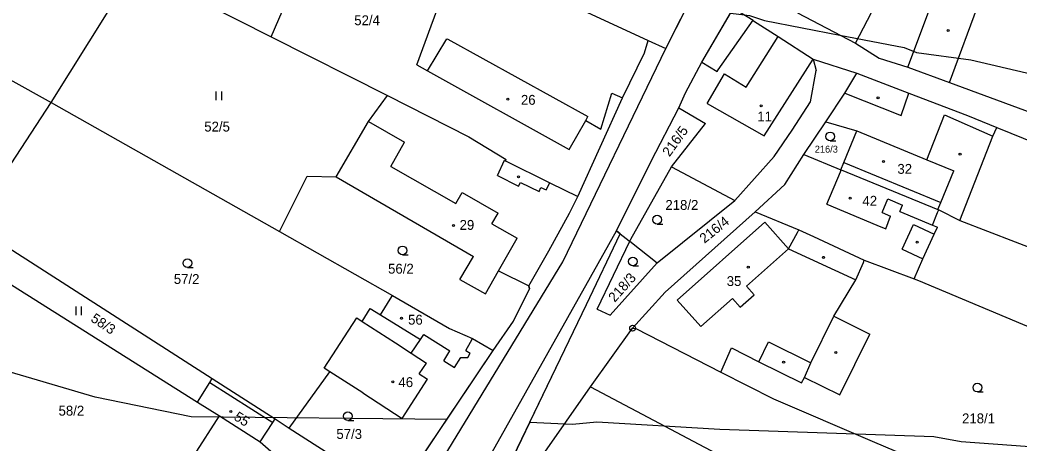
# Model space of a CAD drawing. Extents: x -743888 to -742027, y -1128394 to -1126768.
# Drawn here: x -743087.8 to -742915.5, y -1127647.7 to -1127574.7 of the extents above; entities that cross this region are included whole.
import ezdxf

# ---------------------------------------------------------------- set-up
doc = ezdxf.new("R2010")
doc.units = 0
for name, color, linetype in [('Vrstva 1', 7, 'Continuous'), ('Vrstva 18', 7, 'Continuous'), ('Vrstva 19', 7, 'Continuous'), ('Vrstva 24', 7, 'Continuous'), ('Vrstva 25', 7, 'Continuous'), ('Vrstva 3', 7, 'Continuous'), ('Vrstva 37', 7, 'Continuous'), ('Vrstva 4', 7, 'Continuous'), ('Vrstva 52', 7, 'Continuous'), ('Vrstva 6', 7, 'Continuous')]:
    doc.layers.add(name, color=color, linetype=linetype)

msp = doc.modelspace()

# ---------------------------------------------------------------- linework, layer by layer
at = {"layer": 'Vrstva 1'}
for p, q in [((-743035.35, -1127634.62), (-743029.73, -1127625.98)), ((-743029.73, -1127625.98), (-743028.79, -1127626.59)), ((-743034.37, -1127635.25), (-743035.35, -1127634.62)), ((-743028.68, -1127638.9), (-743034.37, -1127635.25))]:
    msp.add_line(p, q, dxfattribs=at)
for points in [[(-743016.9, -1127575.68), (-743012.24, -1127563.05)], [(-743067.95, -1127565.66), (-743044.5, -1127577.53)], [(-743044.5, -1127577.53), (-743039.4, -1127565.75)], [(-743001.38, -1127568.05), (-742979.47, -1127578.16)], [(-742976.43, -1127579.56), (-742971.19, -1127569.17)], [(-742927.53, -1127585.44), (-742922.25, -1127571.32)], [(-743082.43, -1127588.87), (-743072.64, -1127573.17)], [(-742970.21, -1127581.92), (-742964.75, -1127572.6)], [(-742964.75, -1127572.6), (-742961.39, -1127574.71)], [(-742953.72, -1127573.43), (-742943.72, -1127578.66)], [(-743019.38, -1127582.4), (-743016.9, -1127575.68)], [(-742961.39, -1127574.71), (-742961.32, -1127574.78)], [(-742961.32, -1127574.78), (-742957.06, -1127577.5)], [(-743044.5, -1127577.53), (-743024.44, -1127587.67)], [(-742957.06, -1127577.5), (-742951.01, -1127581.4)], [(-742980.12, -1127580.33), (-742979.47, -1127578.16)], [(-742979.47, -1127578.16), (-742976.43, -1127579.56)], [(-742943.72, -1127578.66), (-742939.64, -1127581.23)], [(-742983.9, -1127588.07), (-742980.12, -1127580.33)], [(-743019.38, -1127582.4), (-743017.56, -1127583.41)], [(-742973.05, -1127587.2), (-742970.21, -1127581.92)], [(-742951.01, -1127581.4), (-742943.48, -1127583.82)], [(-742951.01, -1127581.4), (-742950.51, -1127583.33)], [(-742939.64, -1127581.23), (-742934.7, -1127582.76)], [(-742934.7, -1127582.76), (-742927.53, -1127585.44)], [(-743017.56, -1127583.41), (-742993.08, -1127596.96)], [(-742951.47, -1127588.73), (-742950.51, -1127583.33)], [(-742945.53, -1127587.26), (-742943.48, -1127583.82)], [(-742943.48, -1127583.82), (-742934.51, -1127587.27)], [(-742927.53, -1127585.44), (-742896.8, -1127596.74)], [(-743027.7, -1127592.11), (-743024.44, -1127587.67)], [(-743024.44, -1127587.67), (-743010.42, -1127594.79)], [(-742985.72, -1127587.27), (-742983.9, -1127588.07)], [(-742974.2, -1127589.77), (-742973.05, -1127587.2)], [(-742948.85, -1127592.21), (-742945.53, -1127587.26)], [(-742934.51, -1127587.27), (-742924.42, -1127591.13)], [(-743096.19, -1127609.82), (-743082.43, -1127588.87)], [(-743082.43, -1127588.87), (-743043.08, -1127611.1)], [(-742991.6, -1127605.04), (-742983.9, -1127588.07)], [(-742954.62, -1127593.61), (-742951.47, -1127588.73)], [(-742978.95, -1127598.97), (-742974.2, -1127589.77)], [(-742924.42, -1127591.13), (-742919.33, -1127593.19)], [(-743033.28, -1127601.65), (-743027.7, -1127592.11)], [(-742993.08, -1127596.96), (-742990.26, -1127591.96)], [(-742952.62, -1127597.82), (-742948.85, -1127592.21)], [(-742948.85, -1127592.21), (-742943.5, -1127593.76)], [(-742920.01, -1127594.66), (-742919.33, -1127593.19)], [(-742919.33, -1127593.19), (-742898.48, -1127601.61)], [(-743010.42, -1127594.79), (-743003.98, -1127598.66)], [(-742957.73, -1127598.16), (-742954.62, -1127593.61)], [(-742945.74, -1127599.22), (-742943.5, -1127593.76)], [(-742925.74, -1127609.17), (-742920.01, -1127594.66)], [(-742964.56, -1127605.74), (-742957.73, -1127598.16)], [(-742955.92, -1127602.99), (-742952.62, -1127597.82)], [(-742952.62, -1127597.82), (-742946.24, -1127600.44)], [(-743004.09, -1127598.89), (-743003.98, -1127598.66)], [(-743004.09, -1127598.89), (-742996.47, -1127602.7)], [(-742984.97, -1127610.98), (-742978.95, -1127598.97)], [(-742982.46, -1127612.4), (-742975.48, -1127599.94)], [(-742975.48, -1127599.94), (-742964.56, -1127605.74)], [(-742946.24, -1127600.44), (-742945.74, -1127599.22)], [(-743043.08, -1127611.1), (-743038.28, -1127601.54)], [(-743038.28, -1127601.54), (-743033.28, -1127601.65)], [(-743033.28, -1127601.65), (-743009.6, -1127615.39)], [(-742946.24, -1127600.44), (-742946.19, -1127600.46)], [(-742946.19, -1127600.46), (-742929.52, -1127607.31)], [(-742996.47, -1127602.7), (-742991.6, -1127605.04)], [(-742961.05, -1127607.72), (-742955.92, -1127602.99)], [(-742993.07, -1127607.9), (-742991.6, -1127605.04)], [(-742977.94, -1127616.47), (-742964.56, -1127605.74)], [(-742996.62, -1127614.4), (-742993.07, -1127607.9)], [(-742976.55, -1127621.53), (-742961.05, -1127607.72)], [(-742961.05, -1127607.72), (-742953.51, -1127610.79)], [(-742930.45, -1127609.97), (-742929.56, -1127607.84)], [(-742929.56, -1127607.84), (-742929.36, -1127607.37)], [(-742929.52, -1127607.31), (-742929.36, -1127607.37)], [(-742929.36, -1127607.37), (-742925.74, -1127609.17)], [(-743096.19, -1127609.82), (-743054.68, -1127636.42)], [(-742930.45, -1127609.97), (-742929.58, -1127610.33)], [(-742930.16, -1127611.56), (-742929.58, -1127610.33)], [(-742925.74, -1127609.17), (-742892.31, -1127622.04)], [(-743043.08, -1127611.1), (-743023.57, -1127622.12)], [(-742990.11, -1127623.65), (-742984.29, -1127611.5)], [(-742984.97, -1127610.98), (-742984.29, -1127611.5)], [(-742984.29, -1127611.5), (-742982.75, -1127612.7)], [(-742953.51, -1127610.79), (-742950.98, -1127611.97)], [(-742950.98, -1127611.97), (-742942.21, -1127616.04)], [(-742932.13, -1127615.77), (-742930.16, -1127611.56)], [(-742982.75, -1127612.7), (-742982.64, -1127612.78)], [(-742982.64, -1127612.78), (-742977.94, -1127616.47)], [(-743099.02, -1127614.17), (-743057.24, -1127640.46)], [(-743011.96, -1127619.34), (-743009.6, -1127615.39)], [(-743000.05, -1127620.45), (-742996.62, -1127614.4)], [(-742943.64, -1127619.44), (-742942.36, -1127616.4)], [(-742942.36, -1127616.4), (-742942.21, -1127616.04)], [(-742942.21, -1127616.04), (-742933.59, -1127619.25)], [(-742933.59, -1127619.25), (-742932.13, -1127615.77)], [(-743007.55, -1127621.8), (-743005.29, -1127617.87)], [(-743005.29, -1127617.87), (-743000.05, -1127620.45)], [(-743011.96, -1127619.34), (-743007.55, -1127621.8)], [(-743000.05, -1127620.45), (-742999.93, -1127620.98)], [(-742947.46, -1127625.69), (-742943.64, -1127619.44)], [(-742933.59, -1127619.25), (-742932.84, -1127619.53)], [(-742932.84, -1127619.53), (-742895.2, -1127635.33)], [(-743025.65, -1127625.44), (-743023.67, -1127622.29)], [(-743023.67, -1127622.29), (-743023.57, -1127622.12)], [(-743023.57, -1127622.12), (-743013.72, -1127627.78)], [(-743002.72, -1127626.56), (-742999.93, -1127620.98)], [(-742982.16, -1127627.73), (-742976.55, -1127621.53)], [(-743005.02, -1127654.54), (-742990.11, -1127623.65)], [(-743028.79, -1127626.59), (-743027.43, -1127624.34)], [(-743027.43, -1127624.34), (-743025.65, -1127625.44)], [(-743025.65, -1127625.44), (-743018.73, -1127629.7)], [(-742947.46, -1127625.69), (-742941.23, -1127628.77)], [(-743006.21, -1127631.58), (-743002.72, -1127626.56)], [(-743018.73, -1127629.7), (-743018.16, -1127628.82)], [(-743018.16, -1127628.82), (-743013.67, -1127631.63)], [(-743013.72, -1127627.78), (-743009.79, -1127629.49)], [(-742989.43, -1127637.82), (-742982.16, -1127627.73)], [(-742982.16, -1127627.73), (-742981.61, -1127627.78)], [(-742981.61, -1127627.78), (-742966.93, -1127635.29)], [(-742946.4, -1127639.24), (-742941.23, -1127628.77)], [(-743020.38, -1127632.04), (-743018.73, -1127629.7)], [(-743010.94, -1127631.59), (-743010.14, -1127630.13)], [(-743010.14, -1127630.13), (-743009.79, -1127629.49)], [(-743009.79, -1127629.49), (-743006.21, -1127631.58)], [(-743023.07, -1127656.68), (-743006.21, -1127631.58)], [(-743020.38, -1127632.04), (-743017.73, -1127633.76)], [(-743014.75, -1127633.35), (-743013.67, -1127631.63)], [(-743012.87, -1127634.54), (-743011.82, -1127632.78)], [(-743011.82, -1127632.78), (-743010.61, -1127632.81)], [(-743010.94, -1127631.59), (-743010.16, -1127632.03)], [(-743010.61, -1127632.81), (-743010.16, -1127632.03)], [(-742966.93, -1127635.29), (-742965.09, -1127631.14)], [(-742965.09, -1127631.14), (-742960.41, -1127633.52)], [(-743018.97, -1127635.6), (-743017.73, -1127633.76)], [(-743014.75, -1127633.35), (-743012.87, -1127634.54)], [(-742960.41, -1127633.52), (-742953.01, -1127637.17)], [(-743041.39, -1127644.94), (-743034.37, -1127635.25)], [(-743018.97, -1127635.6), (-743017.55, -1127636.55)], [(-742966.93, -1127635.29), (-742957.86, -1127639.93)], [(-742953.01, -1127637.17), (-742952.54, -1127636.21)], [(-742952.54, -1127636.21), (-742946.4, -1127639.24)], [(-743057.24, -1127640.46), (-743055.09, -1127637.08)], [(-743055.09, -1127637.08), (-743054.68, -1127636.42)], [(-743054.68, -1127636.42), (-743043.83, -1127643.37)], [(-743021.92, -1127643.29), (-743017.55, -1127636.55)], [(-742997.69, -1127649.67), (-742989.43, -1127637.82)], [(-742989.43, -1127637.82), (-742962.79, -1127651.94)], [(-743028.68, -1127638.9), (-743021.92, -1127643.29)], [(-743057.24, -1127640.46), (-743053.43, -1127642.86)], [(-742957.86, -1127639.93), (-742940.86, -1127647.2)], [(-743057.84, -1127649.75), (-743053.43, -1127642.86)], [(-743053.43, -1127642.86), (-743046.41, -1127647.29)], [(-743046.41, -1127647.29), (-743044.24, -1127643.99)], [(-743044.24, -1127643.99), (-743043.83, -1127643.37)], [(-743043.83, -1127643.37), (-743041.39, -1127644.94)], [(-743041.39, -1127644.94), (-743023.07, -1127656.68)], [(-743046.41, -1127647.29), (-743041.85, -1127651.26)], [(-742940.86, -1127647.2), (-742894.92, -1127666.66)]]:
    msp.add_lwpolyline(points, dxfattribs=at)
at = {"layer": 'Vrstva 24'}
msp.add_line((-742982.21, -1127627.73), (-742982.11, -1127627.73), dxfattribs=at)
msp.add_circle((-742982.16, -1127627.73), 0.499, dxfattribs=at)
at = {"layer": 'Vrstva 25'}
for p, q in [((-743054.04, -1127586.97), (-743054.04, -1127588.47)), ((-743053.04, -1127588.47), (-743053.04, -1127586.97)), ((-742948.09, -1127595.45), (-742947.09, -1127595.45)), ((-742977.94, -1127609.8), (-742976.94, -1127609.8)), ((-743021.85, -1127615.09), (-743020.85, -1127615.09)), ((-743058.96, -1127617.29), (-743057.96, -1127617.29)), ((-742982.12, -1127617), (-742981.12, -1127617)), ((-743078.23, -1127623.99), (-743078.23, -1127625.49)), ((-743077.23, -1127625.49), (-743077.23, -1127623.99)), ((-742922.7, -1127638.73), (-742921.7, -1127638.73)), ((-743031.27, -1127643.64), (-743030.27, -1127643.64))]:
    msp.add_line(p, q, dxfattribs=at)
for centre, radius in [((-742927.74, -1127576.46), 0.175), ((-742939.83, -1127588.05), 0.175), ((-743003.7, -1127588.31), 0.175), ((-742960, -1127589.42), 0.175), ((-742948.09, -1127594.7), 0.75), ((-742925.69, -1127597.77), 0.175), ((-742938.88, -1127599.04), 0.175), ((-743001.85, -1127601.67), 0.175), ((-742944.63, -1127605.35), 0.175), ((-742977.94, -1127609.05), 0.75), ((-743013.07, -1127610.05), 0.175), ((-743021.85, -1127614.34), 0.75), ((-742933.07, -1127612.93), 0.175), ((-742982.12, -1127616.25), 0.75), ((-742949.25, -1127615.54), 0.175), ((-743058.96, -1127616.54), 0.75), ((-742962.21, -1127617.23), 0.175), ((-743022.02, -1127626.04), 0.175), ((-742947.1, -1127631.94), 0.175), ((-742956.11, -1127633.58), 0.175), ((-743023.52, -1127636.98), 0.175), ((-742922.7, -1127637.98), 0.75), ((-743051.45, -1127642.11), 0.175), ((-743031.27, -1127642.89), 0.75)]:
    msp.add_circle(centre, radius, dxfattribs=at)
at = {"layer": 'Vrstva 3'}
for points in [[(-742962.56, -1127586.21), (-742957.06, -1127577.5)], [(-742957.06, -1127577.5), (-742951.01, -1127581.4)], [(-743017.56, -1127583.41), (-743014.23, -1127577.87)], [(-743014.23, -1127577.87), (-743014.05, -1127577.97)], [(-743014.05, -1127577.97), (-742989.86, -1127591.25)], [(-742959.5, -1127594.6), (-742951.01, -1127581.4)], [(-743017.56, -1127583.41), (-742993.08, -1127596.96)], [(-742969.28, -1127589.06), (-742966.31, -1127583.91)], [(-742966.31, -1127583.91), (-742962.56, -1127586.21)], [(-742969.28, -1127589.06), (-742959.5, -1127594.6)], [(-742990.26, -1127591.96), (-742989.86, -1127591.25)], [(-743033.28, -1127601.65), (-743027.7, -1127592.11)], [(-743027.7, -1127592.11), (-743021.5, -1127595.7)], [(-742993.08, -1127596.96), (-742990.26, -1127591.96)], [(-742945.74, -1127599.22), (-742943.5, -1127593.76)], [(-742943.5, -1127593.76), (-742931.41, -1127598.72)], [(-743023.86, -1127599.87), (-743021.5, -1127595.7)], [(-743023.86, -1127599.87), (-743012.63, -1127606.25)], [(-742945.74, -1127599.22), (-742929.02, -1127606.08)], [(-742931.41, -1127598.72), (-742926.78, -1127600.62)], [(-743033.28, -1127601.65), (-743009.6, -1127615.39)], [(-742948.66, -1127606.36), (-742946.33, -1127600.8)], [(-742946.33, -1127600.8), (-742946.19, -1127600.46)], [(-742946.19, -1127600.46), (-742929.52, -1127607.31)], [(-742929.02, -1127606.08), (-742926.78, -1127600.62)], [(-743012.63, -1127606.25), (-743011.59, -1127604.36)], [(-743011.59, -1127604.36), (-743005.38, -1127607.91)], [(-742948.66, -1127606.36), (-742940.04, -1127609.97)], [(-742939.14, -1127607.84), (-742938.15, -1127605.48)], [(-742938.15, -1127605.48), (-742935.61, -1127606.55)], [(-742936.05, -1127607.62), (-742935.61, -1127606.55)], [(-743006.43, -1127609.77), (-743005.38, -1127607.91)], [(-742939.14, -1127607.84), (-742937.66, -1127608.47)], [(-742938.46, -1127610.63), (-742937.66, -1127608.47)], [(-742936.05, -1127607.62), (-742930.45, -1127609.97)], [(-742930.45, -1127609.97), (-742929.56, -1127607.84)], [(-742929.56, -1127607.84), (-742929.36, -1127607.37)], [(-742929.52, -1127607.31), (-742929.36, -1127607.37)], [(-743006.43, -1127609.77), (-743002.05, -1127612.26)], [(-742974.48, -1127622.89), (-742959.34, -1127609.47)], [(-742959.34, -1127609.47), (-742955.28, -1127614.06)], [(-742940.04, -1127609.97), (-742938.46, -1127610.63)], [(-743005.29, -1127617.87), (-743002.05, -1127612.26)], [(-743011.96, -1127619.34), (-743009.6, -1127615.39)], [(-742962.53, -1127620.48), (-742955.28, -1127614.06)], [(-743007.55, -1127621.8), (-743005.29, -1127617.87)], [(-743011.96, -1127619.34), (-743007.55, -1127621.8)], [(-742962.53, -1127620.48), (-742961.2, -1127621.98)], [(-743025.65, -1127625.44), (-743023.67, -1127622.29)], [(-743023.67, -1127622.29), (-743023.57, -1127622.12)], [(-743023.57, -1127622.12), (-743013.72, -1127627.78)], [(-742963.62, -1127624.12), (-742961.2, -1127621.98)], [(-742974.48, -1127622.89), (-742970.42, -1127627.47)], [(-742970.42, -1127627.47), (-742964.95, -1127622.62)], [(-742964.95, -1127622.62), (-742963.62, -1127624.12)], [(-743025.65, -1127625.44), (-743018.73, -1127629.7)], [(-743035.35, -1127634.62), (-743029.73, -1127625.98)], [(-743029.73, -1127625.98), (-743028.79, -1127626.59)], [(-743028.79, -1127626.59), (-743023.09, -1127630.28)], [(-743018.73, -1127629.7), (-743018.16, -1127628.82)], [(-743018.16, -1127628.82), (-743013.67, -1127631.63)], [(-743013.72, -1127627.78), (-743009.79, -1127629.49)], [(-743023.09, -1127630.28), (-743020.38, -1127632.04)], [(-743010.94, -1127631.59), (-743010.14, -1127630.13)], [(-743010.14, -1127630.13), (-743009.79, -1127629.49)], [(-743020.38, -1127632.04), (-743017.73, -1127633.76)], [(-743014.75, -1127633.35), (-743013.67, -1127631.63)], [(-743012.87, -1127634.54), (-743011.82, -1127632.78)], [(-743011.82, -1127632.78), (-743010.61, -1127632.81)], [(-743010.94, -1127631.59), (-743010.16, -1127632.03)], [(-743010.61, -1127632.81), (-743010.16, -1127632.03)], [(-743018.97, -1127635.6), (-743017.73, -1127633.76)], [(-743014.75, -1127633.35), (-743012.87, -1127634.54)], [(-743034.37, -1127635.25), (-743035.35, -1127634.62)], [(-743028.68, -1127638.9), (-743034.37, -1127635.25)], [(-743018.97, -1127635.6), (-743017.55, -1127636.55)], [(-743057.24, -1127640.46), (-743055.09, -1127637.08)], [(-743055.09, -1127637.08), (-743044.24, -1127643.99)], [(-743021.92, -1127643.29), (-743017.55, -1127636.55)], [(-743028.68, -1127638.9), (-743021.92, -1127643.29)], [(-743057.24, -1127640.46), (-743053.43, -1127642.86)], [(-743053.43, -1127642.86), (-743046.41, -1127647.29)], [(-743046.41, -1127647.29), (-743044.24, -1127643.99)]]:
    msp.add_lwpolyline(points, dxfattribs=at)
at = {"layer": 'Vrstva 37'}
for centre in [(-743003.7, -1127588.31), (-742960, -1127589.42), (-742938.88, -1127599.04), (-742944.63, -1127605.35), (-743013.07, -1127610.05), (-742962.21, -1127617.23), (-743022.02, -1127626.04), (-743023.52, -1127636.98), (-743051.45, -1127642.11)]:
    msp.add_circle(centre, 0.175, dxfattribs=at)
at = {"layer": 'Vrstva 4'}
msp.add_line((-743028.79, -1127626.59), (-743023.09, -1127630.28), dxfattribs=at)
for points in [[(-742934.7, -1127582.76), (-742929.42, -1127568.64)], [(-742943.72, -1127578.66), (-742940.95, -1127573.36)], [(-742967.39, -1127583.25), (-742961.39, -1127574.71)], [(-742962.56, -1127586.21), (-742957.06, -1127577.5)], [(-743017.56, -1127583.41), (-743014.23, -1127577.87)], [(-743014.23, -1127577.87), (-743014.05, -1127577.97)], [(-743014.05, -1127577.97), (-742989.86, -1127591.25)], [(-742994.19, -1127616.32), (-742976.43, -1127579.56)], [(-742970.21, -1127581.92), (-742967.6, -1127583.54)], [(-742959.5, -1127594.6), (-742951.01, -1127581.4)], [(-742969.28, -1127589.06), (-742966.31, -1127583.91)], [(-742967.6, -1127583.54), (-742967.39, -1127583.25)], [(-742966.31, -1127583.91), (-742962.56, -1127586.21)], [(-742945.53, -1127587.26), (-742935.86, -1127591.09)], [(-742935.86, -1127591.09), (-742934.51, -1127587.27)], [(-742969.28, -1127589.06), (-742959.5, -1127594.6)], [(-742990.26, -1127591.96), (-742989.86, -1127591.25)], [(-742931.41, -1127598.72), (-742928.39, -1127590.97)], [(-742928.39, -1127590.97), (-742920.01, -1127594.66)], [(-743027.7, -1127592.11), (-743021.5, -1127595.7)], [(-742943.5, -1127593.76), (-742931.41, -1127598.72)], [(-743023.86, -1127599.87), (-743021.5, -1127595.7)], [(-743023.86, -1127599.87), (-743012.63, -1127606.25)], [(-743005.46, -1127601.43), (-743004.27, -1127598.8)], [(-743004.27, -1127598.8), (-743004.09, -1127598.89)], [(-742945.74, -1127599.22), (-742929.02, -1127606.08)], [(-742931.41, -1127598.72), (-742926.78, -1127600.62)], [(-743005.46, -1127601.43), (-743001.84, -1127603.28)], [(-742948.66, -1127606.36), (-742946.33, -1127600.8)], [(-742946.33, -1127600.8), (-742946.19, -1127600.46)], [(-742929.02, -1127606.08), (-742926.78, -1127600.62)], [(-743001.84, -1127603.28), (-743001.52, -1127602.66)], [(-743001.52, -1127602.66), (-742998.3, -1127604.18)], [(-742998.3, -1127604.18), (-742997.99, -1127603.52)], [(-742997.99, -1127603.52), (-742997.05, -1127603.92)], [(-742997.05, -1127603.92), (-742996.47, -1127602.7)], [(-743012.63, -1127606.25), (-743011.59, -1127604.36)], [(-743011.59, -1127604.36), (-743005.38, -1127607.91)], [(-742948.66, -1127606.36), (-742940.04, -1127609.97)], [(-742939.14, -1127607.84), (-742938.15, -1127605.48)], [(-742938.15, -1127605.48), (-742935.61, -1127606.55)], [(-742936.05, -1127607.62), (-742935.61, -1127606.55)], [(-742929.52, -1127607.31), (-742929.02, -1127606.08)], [(-743006.43, -1127609.77), (-743005.38, -1127607.91)], [(-742939.14, -1127607.84), (-742937.66, -1127608.47)], [(-742938.46, -1127610.63), (-742937.66, -1127608.47)], [(-742936.05, -1127607.62), (-742930.45, -1127609.97)], [(-743006.43, -1127609.77), (-743002.05, -1127612.26)], [(-742974.48, -1127622.89), (-742959.34, -1127609.47)], [(-742959.34, -1127609.47), (-742955.28, -1127614.06)], [(-742940.04, -1127609.97), (-742938.46, -1127610.63)], [(-742935.66, -1127614.11), (-742933.69, -1127609.9)], [(-742933.69, -1127609.9), (-742930.16, -1127611.56)], [(-742989.42, -1127618.93), (-742984.97, -1127610.98)], [(-742955.28, -1127614.06), (-742953.75, -1127611.23)], [(-742953.75, -1127611.23), (-742953.51, -1127610.79)], [(-743005.29, -1127617.87), (-743002.05, -1127612.26)], [(-742962.53, -1127620.48), (-742955.28, -1127614.06)], [(-742955.28, -1127614.06), (-742943.64, -1127619.44)], [(-742935.66, -1127614.11), (-742932.13, -1127615.77)], [(-743020.57, -1127659.55), (-742994.19, -1127616.32)], [(-743007.93, -1127651.85), (-742989.42, -1127618.93)], [(-742962.53, -1127620.48), (-742961.2, -1127621.98)], [(-742963.62, -1127624.12), (-742961.2, -1127621.98)], [(-742974.48, -1127622.89), (-742970.42, -1127627.47)], [(-742970.42, -1127627.47), (-742964.95, -1127622.62)], [(-742964.95, -1127622.62), (-742963.62, -1127624.12)], [(-742951.41, -1127633.7), (-742947.46, -1127625.69)], [(-743023.09, -1127630.28), (-743020.38, -1127632.04)], [(-742960.41, -1127633.52), (-742958.72, -1127630.09)], [(-742958.72, -1127630.09), (-742951.41, -1127633.7)], [(-742952.54, -1127636.21), (-742951.41, -1127633.7)], [(-743055.09, -1127637.08), (-743044.24, -1127643.99)]]:
    msp.add_lwpolyline(points, dxfattribs=at)
at = {"layer": 'Vrstva 52'}
for points in [[(-743014.19, -1127643.46), (-743006.21, -1127631.58), (-743002.72, -1127626.56), (-742999.93, -1127620.98), (-743000.05, -1127620.45), (-742996.62, -1127614.4), (-742993.07, -1127607.9), (-742991.6, -1127605.04), (-742983.9, -1127588.07), (-742980.12, -1127580.33), (-742979.47, -1127578.16), (-742976.43, -1127579.56), (-742972.89, -1127572.54)], [(-742999.9, -1127643.94), (-742990.11, -1127623.65), (-742984.29, -1127611.5), (-742984.97, -1127610.98), (-742978.95, -1127598.97), (-742974.2, -1127589.77), (-742973.05, -1127587.2), (-742970.21, -1127581.92), (-742965.26, -1127573.48)], [(-742965.26, -1127573.48), (-742962.89, -1127573.77), (-742962, -1127573.88), (-742959.44, -1127574.75), (-742946.43, -1127577.24), (-742935.31, -1127579.38), (-742933.19, -1127580.25), (-742923.81, -1127581.5), (-742895, -1127588.25), (-742870.38, -1127595.5), (-742826.25, -1127613.38), (-742782.56, -1127629.88), (-742777.06, -1127632.88), (-742760.94, -1127638.75), (-742741, -1127643.5)], [(-743014.19, -1127643.46), (-743058.31, -1127643), (-743074.88, -1127639.63), (-743097.75, -1127632.88)], [(-743053.67, -1127722.32), (-743052.52, -1127708.86), (-743050.26, -1127695.79), (-743044.97, -1127687.73), (-743040.96, -1127682.5), (-743037.58, -1127678), (-743034.56, -1127673.98), (-743031.72, -1127669.85), (-743026.2, -1127661.44), (-743023.07, -1127656.68), (-743014.19, -1127643.46)], [(-742999.9, -1127643.94), (-743005.02, -1127654.54), (-743028.72, -1127682.17), (-743035.1, -1127691.53), (-743041.92, -1127706.05), (-743043.55, -1127712.08), (-743043.57, -1127712.76), (-743042.89, -1127720.23), (-743043.04, -1127722.81), (-743039.23, -1127734.18)], [(-742999.9, -1127643.94), (-742993.87, -1127644.19), (-742992.56, -1127644.25), (-742988.31, -1127643.88), (-742967.13, -1127645.13), (-742930.19, -1127646.38), (-742925.5, -1127647.25), (-742908.13, -1127648.5), (-742903.88, -1127649.38), (-742871.63, -1127651.5), (-742867.81, -1127651.13), (-742864, -1127652.38), (-742831.75, -1127656.13), (-742820.75, -1127657.5), (-742802.94, -1127658.75), (-742777.06, -1127663), (-742726.13, -1127679.88)]]:
    msp.add_lwpolyline(points, dxfattribs=at)
at = {"layer": 'Vrstva 6'}
for points in [[(-743239.89, -1127501.37), (-743082.43, -1127588.87)], [(-742987.63, -1127593.44), (-742985.72, -1127587.27)], [(-742974.2, -1127589.77), (-742969.61, -1127592.47)], [(-742990.26, -1127591.96), (-742987.63, -1127593.44)], [(-742975.48, -1127599.94), (-742969.61, -1127592.47)], [(-742988.28, -1127624.48), (-742982.64, -1127612.78)], [(-742982.64, -1127612.78), (-742982.46, -1127612.4)], [(-742986.05, -1127625.51), (-742977.94, -1127616.47)], [(-742988.28, -1127624.48), (-742986.05, -1127625.51)]]:
    msp.add_lwpolyline(points, dxfattribs=at)

# ---------------------------------------------------------------- texts
at = {"layer": 'Vrstva 18'}
for s, height, p in [('52/4', 1.7, (-743030.18, -1127575.55)), ('52/5', 1.7, (-743056.05, -1127593.87)), ('216/3', 1.19, (-742950.74, -1127597.5)), ('218/2', 1.7, (-742976.51, -1127607.36)), ('56/2', 1.7, (-743024.34, -1127618.35)), ('57/2', 1.7, (-743061.3, -1127620.12)), ('58/2', 1.7, (-743081.18, -1127642.8)), ('218/1', 1.7, (-742925.34, -1127644.13)), ('57/3', 1.7, (-743033.26, -1127646.82))]:
    msp.add_text(s, height=height, dxfattribs=at).set_placement(p)
for s, rotation, p in [('216/5', 54.3946, (-742975.8, -1127598.32)), ('216/4', 38.7143, (-742969.77, -1127613.21)), ('218/3', 48.0574, (-742985.25, -1127623.39)), ('58/3', 326.2452, (-743075.77, -1127626.45))]:
    msp.add_text(s, height=1.7, rotation=rotation, dxfattribs=at).set_placement(p)
at = {"layer": 'Vrstva 19'}
for s, p in [('26', (-743001.43, -1127589.26)), ('11', (-742960.66, -1127592.13)), ('32', (-742936.49, -1127601.15)), ('42', (-742942.52, -1127606.65)), ('29', (-743012.01, -1127610.8)), ('35', (-742965.93, -1127620.48)), ('56', (-743020.89, -1127627.13)), ('46', (-743022.55, -1127637.89))]:
    msp.add_text(s, height=1.7, dxfattribs=at).set_placement(p)
msp.add_text('55', height=1.7, rotation=327.7713, dxfattribs=at).set_placement((-743051.07, -1127643.43))

doc.saveas('drawing.dxf')
